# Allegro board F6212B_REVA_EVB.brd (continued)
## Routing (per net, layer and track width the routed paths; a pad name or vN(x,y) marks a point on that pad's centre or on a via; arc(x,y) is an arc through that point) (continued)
VDD: length 39.1
  TOP w0.165: C7.2 v1(43.33,49.58)
  TOP w0.508: C3.2 C4.2 C1.2 35.51,93.58 J16.6
  BOTTOM w0.254: 35.52,92.57 J16.6 ; J16.6 34.5,93.6 ; J16.6 36.55,93.6 ; J16.6 35.52,94.63 ; J16.4 39.09,93.6 ; J16.4 38.06,92.57 ; J16.4 38.06,94.63 ; J16.4 37.04,93.6 ; J29.3 51.69,63.83 ; J29.3 50.66,62.8 ; J29.3 49.63,63.83 ; J29.3 50.66,64.86 ; TP6.1 44.45,52.97 ; TP6.1 45.99,51.44 ; TP6.1 44.45,49.9 ; TP6.1 42.91,51.44 ; 39.58,93.6 J16.2 ; J16.2 41.63,93.6 ; J16.2 40.6,94.63 ; J16.2 40.6,92.57 ; J16.12 28.93,93.6 ; J16.12 27.9,92.57 ; J16.12 27.9,94.63 ; J16.10 30.44,94.63 ; J16.10 30.44,92.57 ; J16.10 31.47,93.6 ; J16.10 29.42,93.6 ; 32.98,92.57 J16.8 ; J16.8 34.01,93.6 ; J16.8 32.98,94.63 ; J16.8 31.96,93.6
  vias: v1(57.63,42.53) v1(57.63,41.5) v1(57.61,40.5) v1(57.89,42.28) v1(57.91,41.25) v1(57.92,40.22) v1(59.93,42.53) v1(60.21,42.27) v1(74.24,54.75) v1(74.26,53.43) v1(74.52,54.5) v1(74.52,53.16) v2(51.48,42.4) v2(51.48,41.4) v2(51.48,40.4) v2(54.48,42.4) v2(54.48,41.4) v2(54.48,40.4)
VDD_CREG: length 56.2
  TOP w0.508: R20.2 53.01,49.96 52.19,50.79 52.19,56.66 TP4.1 53.04,58.94 44.6,67.38 J14.1 ; J14.1 J13.1 J12.1 J11.3 ; J14.1 44.59,77.99 C8.2 42.18,77.98 J15.3 J28.3
VDD_EXT: length 3.4
  TOP w0.254: J29.1 59.03,63.83 TP1.1
VDDB: length 4.6
  TOP w0.508: C21.2 C22.2 C23.2 25.37,93.59 J16.14
  vias: v1(48.08,45.06) v1(48.09,37.52) v1(48.34,45.34) v1(48.37,37.8) v1(48.92,46.08) v1(48.93,36.47) v1(49.2,46.34) v1(49.23,36.77) v1(56.77,46.36) v1(56.77,36.74) v1(57.06,46.06) v1(57.04,36.47) v1(57.63,45.36) v1(57.63,37.8) v1(57.91,45.07) v1(57.9,37.5) v2(50.48,43.4) v2(50.48,39.4) v2(50.98,43.9) v2(50.98,38.9) v2(54.98,43.9) v2(54.98,38.9) v2(55.48,43.4) v2(55.48,39.4)
ADD1: length 46.4
  L2 w0.127: J11.2 55.46,78.68 55.46,77.44 54.27,76.25 50.39,76.25 48.3,74.16 48.3,61.33 53.76,55.87 53.76,46.81 53.87,46.7 53.87,45.87 v1(53.33,45.33)
  BOTTOM w0.165: v2(53.98,42.9) 53.98,44.68 v1(53.33,45.33)
ADD2: length 42.7
  L2 w0.127: J12.2 47.88,75.16 47.88,61.33 53.49,55.71 53.49,46.7 53.62,46.57 53.62,46.15 v1(53.31,45.85)
  BOTTOM w0.165: v1(53.31,45.85) 52.93,45.46 52.93,45.07 53.48,44.51 v2(53.48,42.9)
ADD3: length 41.4
  L2 w0.127: v1(52.21,45.39) 52.9,46.08 52.9,55.44 47.03,61.3 47.03,78.8 J13.2
  BOTTOM w0.165: v1(52.21,45.39) 52.21,44.69 52.98,43.92 v2(52.98,42.9)
ADD4: length 41.5
  L2 w0.127: J14.2 46.6,78.52 46.6,61.28 52.6,55.27 52.6,46.41 v1(52.21,46.01)
  BOTTOM w0.165: v2(52.48,42.9) 52.48,43.96 51.84,44.6 51.84,45.64 v1(52.21,46.01)
ADD5: length 43.2
  L2 w0.127: J15.2 46.16,74.71 46.16,61.28 52.35,55.09 52.35,46.66 51.51,45.82 51.51,45.81 v1(51.47,45.77)
  BOTTOM w0.165: v2(51.98,42.9) 51.98,43.98 51.51,44.45 51.51,45.72 v1(51.47,45.77)
AOUT: length 37.5
  TOP w0.165: R4.2 v1(55.59,71.7)
  L2 w0.254: v3(56.48,41.4) 55.71,41.4 55.23,41.88 55.23,42.95 53.98,44.21 53.98,45.14 54.41,45.57 54.41,46.93 54.25,47.08 54.25,56.46 49.05,61.67 49.05,65.16 v1(55.59,71.7)
CREG: length 4.4
  TOP w0.165: R20.1 52.02,48.22 C9.1 51.87,48.07 51.87,46.18 51.84,46.16 51.84,45.05 U3.A6
CSB: length 46.3
  TOP w0.127: R12.2 R13.2
  TOP w0.165: R30.2 74.43,76.17 73.77,75.51 71.12,75.51 70.03,74.42 70.03,68.89 68.48,67.34 65.53,67.34 53.52,55.32 53.52,55.13 53.48,55.09 53.48,47.79 52.58,46.89 52.58,45 U3.A7
F2232H_CSB: length 3.3
  TOP w0.165: J22.12 72.54,79.55 73.51,78.59 R12.1
F2232H_MODE: length 2.7
  TOP w0.165: R32.1 84.25,78.97 J22.4
F2232H_RESET: length 2.8
  TOP w0.165: R10.1 79.48,78.66 J22.8
F2232H_SCLK: length 3
  TOP w0.165: J22.16 66.6,80.52 65.9,79.82 R14.1
F2232H_SDI: length 4.1
  TOP w0.165: J22.18 64.31,79.91 63.72,79.91 62.4,78.59 R16.1
MODE: length 59.4
  TOP w0.165: R31.2 83.64,77.9 83.64,78.33 82.7,79.27 79.62,79.27 78.89,80 78.89,84.72 78.24,85.37 35.56,85.37 34.11,83.92 R3.1
PPMU_CSB: length 24.1
  TOP w0.165: R30.1 v1(73.34,76.92) ; U4.48 v1(60.15,90.93)
  L2 w0.127: v1(60.15,90.93) 63.96,87.12 68.58,87.12 71.3,84.4 71.3,79.6 73.34,77.56 v1(73.34,76.92)
PPMU_MODE: length 39
  TOP w0.165: R31.1 v1(83.12,77.97) ; U4.57 v1(56.15,95.17)
  L2 w0.127: v1(83.12,77.97) 81.46,79.63 81.46,85.09 77.14,89.41 65.33,89.41 61.7,93.04 58.28,93.04 v1(56.15,95.17)
PPMU_RESET: length 34.4
  TOP w0.165: U4.56 v1(56.95,90.93) ; R33.1 v1(78.32,77.99)
  L2 w0.127: v1(78.32,77.99) 78.92,78.59 78.92,84.68 75.41,88.19 64.95,88.19 60.99,92.15 58.17,92.15 v1(56.95,90.93)
PPMU_SCLK: length 21.7
  TOP w0.165: U4.45 v1(60.95,95.19) ; R28.1 v1(64.77,78.08)
  BOTTOM w0.165: v1(60.95,95.19) 60.95,79.51 62.38,78.08 v1(64.77,78.08)
PPMU_SDI: length 19.9
  TOP w0.165: U4.53 v1(57.75,95.17) ; R27.1 v1(60.46,78.13)
  BOTTOM w0.165: v1(60.46,78.13) 58.9,79.69 58.9,94.02 v1(57.75,95.17)
PPMU_SDO: length 24.6
  TOP w0.165: R29.1 v1(68.87,78.03) ; U4.60 v1(55.35,90.93)
  L2 w0.127: v1(55.35,90.93) 60.03,86.26 67.21,86.26 68.87,84.59 v1(68.87,78.03)
RESET: length 69
  TOP w0.165: v1(79.5,76.78) 79.41,76.87 R33.2 ; R10.2 80.64,77.38 R11.2
  L2 w0.127: v1(53.24,46.36) 53.24,55.56 47.45,61.35 v1(47.45,75.64)
  BOTTOM w0.165: v1(53.24,46.36) 53.24,46.34 52.57,45.68 52.57,44.81 v2(52.98,44.4) ; v1(47.45,75.64) 59.33,75.64 61.11,77.42 78.87,77.42 v1(79.5,76.78)
RF1: length 47.6
  L2 w0.203: v3(50.48,44.9) 50.48,47.9 arc(49.5,52.87) 46.69,57.07 arc(35.35,64.65) 21.97,67.31 v4(14.96,67.31)
RF2: length 47.6
  L2 w0.203: v4(3.51,50.04) 26.75,50.04 arc(30.27,49.34) 33.25,47.35 arc(37.06,44.8) 41.56,43.9 v3(49.48,43.9)
RF3: length 47.6
  L2 w0.203: v4(3.51,32.77) 26.75,32.77 arc(30.27,33.47) 33.25,35.46 arc(37.06,38.01) 41.56,38.9 v3(49.48,38.9)
RF4: length 47.6
  L2 w0.203: v3(50.48,37.9) 50.48,34.9 arc(49.5,29.94) 46.69,25.73 arc(35.35,18.15) 21.97,15.49 v4(14.96,15.49)
RF5: length 47.6
  L2 w0.203: v4(91.01,15.49) 84,15.49 arc(70.62,18.15) 59.28,25.73 arc(56.47,29.94) 55.48,34.9 v3(55.48,37.9)
RF6: length 47.6
  L2 w0.203: v4(102.46,32.77) 79.22,32.77 arc(75.7,33.47) 72.72,35.46 arc(68.91,38.01) 64.41,38.9 v3(56.48,38.9)
RF7: length 47.6
  L2 w0.203: v3(56.48,43.9) 64.41,43.9 arc(68.91,44.8) 72.72,47.35 arc(75.7,49.34) 79.22,50.04 v4(102.46,50.04)
RF8: length 47.6
  L2 w0.203: v4(91.01,67.31) 84,67.31 arc(70.62,64.65) 59.28,57.07 arc(56.47,52.87) 55.48,47.9 v3(55.48,44.9)
RFC1: length 37.5
  L2 w0.203: v4(42.82,3.51) 42.82,8.71 arc(43.4,11.62) 45.05,14.09 49.56,18.6 arc(51.35,21.28) 51.98,24.45 v3(51.98,37.9)
RFC2: length 37.5
  L2 w0.203: v4(63.14,3.51) 63.14,8.71 arc(62.57,11.62) 60.92,14.09 56.41,18.6 arc(54.61,21.28) 53.98,24.45 v3(53.98,37.9)
SCLK: length 46.4
  TOP w0.127: R28.2 R14.2
  TOP w0.165: R14.2 R15.2 ; v1(70.39,74.1) 70.39,68.67 68.61,66.88 65.68,66.88 53.77,54.97 53.77,47.57 52.88,46.68 52.88,45.01 U3.A8 ; v1(65.86,76.84) R28.2
  BOTTOM w0.165: v1(70.39,74.1) 70.39,75.53 69.09,76.84 v1(65.86,76.84)
SDI: length 50.7
  TOP w0.165: U3.A10 54.23,45.15 54.23,46.86 54.43,47.07 54.43,54.46 66.01,66.04 68.91,66.04 71.15,68.28 v1(71.15,72.77) ; R17.2 62.64,77.5 R16.2 61.57,77.44 v1(61.57,76.84)
  BOTTOM w0.165: v1(71.15,72.77) 70.64,72.77 69.88,73.53 69.88,75.31 68.73,76.45 65.46,76.45 65.07,76.84 v1(61.57,76.84)
SDO: length 41.8
  TOP w0.165: U3.A9 53.8,45.21 53.8,47.02 54.13,47.35 54.13,54.74 65.84,66.45 68.71,66.45 70.76,68.5 v1(70.76,74.41) ; R29.2 v1(69.96,76.9)
  BOTTOM w0.165: v1(69.96,76.9) 70.76,76.1 v1(70.76,74.41)
TRIG: length 62.4
  TOP w0.165: J30.1 29.69,80.72 35.52,86.54 79.37,86.54 81.42,84.49 81.42,81.78 J22.6
N411943: length 2.6
  TOP w0.165: R2.1 R1.1 U3.H1
N412142: length 13.5
  TOP w0.165: TP3.1 34.96,42.44 R2.2
N417748: length 52.6
  TOP w0.165: R3.2 34.12,80.52 J28.2
  L2 w0.127: v1(51.47,46.38) 51.47,46.39 52.07,46.99 52.07,48.68 51.59,49.16 51.59,49.5 52.01,49.92 52.01,54.99 45.75,61.25 45.75,70.79 J28.2
  BOTTOM w0.165: v1(51.47,46.38) 51.08,45.99 51.08,44.35 51.36,44.07 51.36,43.19 50.95,42.79 50.95,39.89 51.31,39.54 52.63,39.54 52.98,39.89 v2(52.98,39.9)
N421198: length 3.1
  TOP w0.165: R25.2 53.92,70.69 R4.1 53.92,73.7 J26.1
N421279: length 2.1
  TOP w0.165: R5.2 51.42,71.69 J26.2
N422340: length 3.6
  TOP w0.165: R6.2 55.49,68.11 R7.1 55.45,69.14 C13.2 53.98,69.16 U2.4
N422374: length 10.5
  TOP w0.165: U2.1 52,66.19 52.4,65.79 55.19,65.79 R6.1 56.21,66.08 57.34,67.21 57.34,68.39 C13.1 R9.2
N464793: length 7.9
  TOP w0.165: C10.2 51.22,69.23 ; 51.22,69.23 51.98,69.23 U2.5 ; 51.22,69.23 51.17,69.18 51.17,65.86 J29.2
N485360: length 3
  TOP w0.165: J22.14 R18.1 R19.2
N575389: length 1.4
  TOP w0.127: C20.1 61.21,42.41 R26.2
N719451: length 1
  TOP w0.165: R15.1 C15.2
N722947: length 1.1
  TOP w0.165: R19.1 72.17,77.55 C17.2
N724495: length 1.3
  TOP w0.127: R13.1 C14.2
N739084: length 1.3
  TOP w0.165: R11.1 C12.2
N4197900: length 4.1
  TOP w0.165: R25.1 52.81,68.49 53.9,67.4 U2.3
N4219901: length 8.8
  TOP w0.165: J21.1 65.33,72.07 58.71,72.07 57.66,71.02 R9.1

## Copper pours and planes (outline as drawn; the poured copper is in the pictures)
GND on TOP (solid shape): outline of 205 points within 0,43.69 7.47,56.39
GND on TOP (solid shape): outline of 205 points within 98.5,26.42 105.97,39.12
GND on TOP (solid shape): outline of 207 points within 0,26.42 7.47,39.12
GND on TOP (solid shape): outline of 207 points within 98.5,43.69 105.97,56.39
GND on TOP (solid shape): outline of 211 points within 87.05,60.96 94.51,73.66
GND on TOP (solid shape): outline of 220 points within 11.46,60.96 18.92,73.66
GND on TOP (solid shape): outline of 220 points within 11.46,9.14 18.92,21.84
GND on TOP (solid shape): outline of 220 points within 36.47,0 49.17,7.47
GND on TOP (solid shape): outline of 220 points within 56.79,0 69.49,7.47
GND on TOP (solid shape): outline of 220 points within 87.05,9.14 94.51,21.84
GND on TOP: 11.46,25.41 0,25.41 0,26.78 7.19,26.78 7.18,38.75 0,38.75 0,44.07 7.15,44.07 7.15,55.99 0,55.99 0,57.39 11.46,57.39 11.46,61.14 18.57,61.14 18.55,73.48 11.46,73.48 11.46,100.44 94.51,100.44 94.51,73.29 87.3,73.29 87.29,61.33 94.51,61.31 94.51,57.39 105.97,57.39 105.97,56.02 98.87,56.02 98.84,44.04 105.97,44.04 105.97,38.73 98.75,38.75 98.79,26.81 105.97,26.81 105.95,25.41 94.51,25.41 94.51,21.46 87.35,21.46 87.35,9.54 94.48,9.54 94.51,0 69.13,0 69.13,7.18 57.2,7.17 57.21,0 48.81,0 48.8,7.13 36.84,7.12 36.84,0 11.46,0 11.46,9.56 18.54,9.56 18.54,21.44 11.46,21.44
GND on BOTTOM, L3: 11.46,25.41 0,25.41 0,57.39 11.46,57.39 11.46,100.44 94.51,100.44 94.51,57.39 105.97,57.39 105.97,25.41 94.51,25.41 94.51,0 11.46,0
GND on L2: 7.47,56.39 0,56.39 0,43.69 7.47,43.69 7.47,49.71 3.76,49.71 3.09,50.04 3.76,50.37 7.47,50.37
GND on L2: 56.79,7.47 56.79,0 69.49,0 69.49,7.47 63.47,7.47 63.47,3.76 63.14,3.09 62.81,3.76 62.81,7.47
GND on L2: 98.49,26.42 105.96,26.42 105.96,39.12 98.49,39.12 98.49,33.1 102.19,33.1 102.86,32.77 102.19,32.44 98.49,32.44
GND on L2: 18.92,73.66 11.46,73.66 11.46,60.96 18.92,60.96 18.92,66.98 15.22,66.98 14.55,67.31 15.22,67.64 18.92,67.64
GND on L2: 98.5,43.69 105.96,43.69 105.96,56.39 98.5,56.39 98.5,50.37 102.2,50.37 102.87,50.04 102.2,49.71 98.5,49.71
GND on L2: 7.47,39.12 0,39.12 0,26.42 7.47,26.42 7.47,32.44 3.76,32.44 3.09,32.77 3.76,33.1 7.47,33.1
GND on L2: 11.46,25.41 0,25.41 0,26.78 7.19,26.78 7.18,38.75 0,38.75 0,44.07 7.15,44.07 7.15,55.99 0,55.99 0,57.39 11.46,57.39 11.46,61.33 18.47,61.33 18.45,73.27 11.46,73.27 11.46,100.44 94.51,100.44 94.51,73.29 87.3,73.29 87.29,61.33 94.51,61.31 94.51,57.39 105.97,57.39 105.97,56.02 98.82,56.02 98.79,44.04 105.97,44.04 105.97,38.73 98.75,38.75 98.79,26.81 105.97,26.81 105.95,25.41 94.51,25.41 94.51,21.46 87.35,21.46 87.35,9.54 94.48,9.54 94.51,0 69.13,0 69.13,7.18 57.2,7.17 57.21,0 48.81,0 48.8,7.13 36.84,7.12 36.84,0 11.46,0 11.46,9.56 18.59,9.56 18.59,21.44 11.46,21.44 ; 10 cut-outs
GND on L2: 87.05,60.96 94.51,60.96 94.51,73.66 87.05,73.66 87.05,67.64 90.75,67.64 91.42,67.31 90.75,66.98 87.05,66.98
GND on L2: 18.92,21.84 11.45,21.84 11.45,9.14 18.92,9.14 18.92,15.16 15.22,15.16 14.55,15.49 15.22,15.82 18.92,15.82
GND on L2: 36.47,7.47 36.47,0 49.17,0 49.17,7.47 43.15,7.47 43.15,3.76 42.82,3.09 42.49,3.76 42.49,7.47
GND on L2: 87.05,9.14 94.51,9.14 94.51,21.84 87.05,21.84 87.05,15.82 90.75,15.82 91.42,15.49 90.75,15.16 87.05,15.16
VDD on BOTTOM: 26.95,94.87 42.32,94.87 42.32,91.52 33.5,82.7 33.5,71.27 39.52,65.25 70.74,65.25 74.83,61.16 74.83,43.76 71.12,40.06 53.26,40.06 53.14,40.18 52.84,40.18 52.72,40.06 51.31,40.06 51.16,40.21 51.16,42.37 51.38,42.6 54.28,42.6 54.43,42.75 56.24,42.75 57.63,44.15 59.28,44.15 59.28,50.67 48.16,50.67 47.55,50.68 43.7,46.86 38.13,46.86 26.95,58.04
VDDB on BOTTOM: 20.02,94.77 26.57,94.77 26.57,89.7 26.21,89.23 26.21,57.63 37.62,46.23 43.97,46.23 47.8,50.06 58.6,50.06 58.6,44.65 57.43,44.65 55.8,43.03 55.24,43.03 53.82,44.47 53.82,46.66 50.93,46.66 50.93,44.81 51.31,44.38 51.31,43.49 50.72,42.9 50.72,39.8 51.33,39.19 54.58,39.19 55.19,39.8 55.78,39.8 56.16,39.42 58.42,39.42 58.42,34.06 57.66,33.3 34.9,33.3 20.02,48.18
(no net) on TOP: 102.75,50.34 105.08,50.34 105.97,50.54 105.97,56.39 98.5,56.39 98.5,43.69 105.97,43.69 105.97,49.54 105.08,49.73 102.75,49.73 102.66,49.67 102.56,49.63 102.45,49.62 102.35,49.63 102.25,49.68 102.16,49.74 102.1,49.83 102.06,49.93 102.04,50.04 102.06,50.15 102.1,50.25 102.16,50.33 102.25,50.4 102.35,50.44 102.45,50.46 102.56,50.45 102.66,50.41
(no net) on TOP: 14.67,15.19 12.34,15.19 11.46,15 11.46,9.14 18.92,9.14 18.92,21.84 11.46,21.84 11.46,15.99 12.34,15.8 14.67,15.8 14.76,15.86 14.86,15.9 14.97,15.91 15.08,15.9 15.18,15.85 15.26,15.79 15.33,15.7 15.37,15.6 15.38,15.49 15.37,15.39 15.33,15.29 15.26,15.2 15.18,15.13 15.08,15.09 14.97,15.07 14.86,15.09 14.76,15.13
(no net) on TOP: 3.22,49.73 0.89,49.73 0,49.54 0,43.69 7.47,43.69 7.47,56.39 0,56.39 0,50.54 0.89,50.34 3.22,50.34 3.31,50.41 3.41,50.45 3.51,50.46 3.62,50.44 3.72,50.4 3.81,50.33 3.87,50.25 3.91,50.15 3.93,50.04 3.91,49.93 3.87,49.83 3.81,49.74 3.72,49.68 3.62,49.63 3.51,49.62 3.41,49.63 3.31,49.67
(no net) on TOP: 102.75,33.07 105.08,33.07 105.97,33.26 105.97,39.12 98.5,39.12 98.5,26.42 105.97,26.42 105.97,32.27 105.08,32.46 102.75,32.46 102.66,32.4 102.56,32.36 102.45,32.35 102.35,32.36 102.25,32.41 102.16,32.47 102.1,32.56 102.06,32.66 102.04,32.77 102.06,32.87 102.1,32.97 102.16,33.06 102.25,33.13 102.35,33.17 102.45,33.19 102.56,33.17 102.66,33.13
(no net) on TOP: 91.3,15.8 93.62,15.8 94.51,15.99 94.51,21.84 87.05,21.84 87.05,9.14 94.51,9.14 94.51,15 93.62,15.19 91.3,15.19 91.21,15.13 91.11,15.09 91,15.07 90.89,15.09 90.79,15.13 90.71,15.2 90.64,15.29 90.6,15.39 90.59,15.49 90.6,15.6 90.64,15.7 90.71,15.79 90.79,15.85 90.89,15.9 91,15.91 91.11,15.9 91.21,15.86
(no net) on TOP: 43.13,3.22 43.13,0.89 43.32,0 49.17,0 49.17,7.47 36.47,7.47 36.47,0 42.33,0 42.52,0.89 42.52,3.22 42.46,3.31 42.42,3.41 42.41,3.51 42.42,3.62 42.46,3.72 42.53,3.81 42.62,3.87 42.72,3.91 42.82,3.93 42.93,3.91 43.03,3.87 43.12,3.81 43.18,3.72 43.23,3.62 43.24,3.51 43.23,3.41 43.19,3.31
(no net) on TOP: 63.45,3.22 63.45,0.89 63.64,0 69.49,0 69.49,7.47 56.79,7.47 56.79,0 62.65,0 62.84,0.89 62.84,3.22 62.78,3.31 62.74,3.41 62.73,3.51 62.74,3.62 62.78,3.72 62.85,3.81 62.94,3.87 63.04,3.91 63.14,3.93 63.25,3.91 63.35,3.87 63.44,3.81 63.5,3.72 63.55,3.62 63.56,3.51 63.55,3.41 63.51,3.31
(no net) on TOP: 14.67,67.01 12.34,67.01 11.46,66.81 11.46,60.96 18.92,60.96 18.92,73.66 11.46,73.66 11.46,67.81 12.34,67.61 14.67,67.61 14.76,67.68 14.86,67.72 14.97,67.73 15.08,67.71 15.18,67.67 15.26,67.6 15.33,67.52 15.37,67.42 15.38,67.31 15.37,67.2 15.33,67.1 15.26,67.02 15.18,66.95 15.08,66.91 14.97,66.89 14.86,66.9 14.76,66.94
(no net) on TOP: 91.29,67.61 93.62,67.61 94.51,67.81 94.51,73.66 87.05,73.66 87.05,60.96 94.51,60.96 94.51,66.81 93.62,67.01 91.29,67.01 91.21,66.94 91.11,66.9 91,66.89 90.89,66.91 90.79,66.95 90.71,67.02 90.64,67.1 90.6,67.2 90.59,67.31 90.6,67.42 90.64,67.52 90.71,67.6 90.79,67.67 90.89,67.71 91,67.73 91.11,67.72 91.21,67.68
(no net) on TOP: 3.22,32.46 0.89,32.46 0,32.27 0,26.42 7.47,26.42 7.47,39.12 0,39.12 0,33.26 0.89,33.07 3.22,33.07 3.31,33.13 3.41,33.17 3.51,33.19 3.62,33.17 3.72,33.13 3.81,33.06 3.87,32.97 3.91,32.87 3.93,32.77 3.91,32.66 3.87,32.56 3.81,32.47 3.72,32.41 3.62,32.36 3.51,32.35 3.41,32.36 3.31,32.4

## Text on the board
Ref Des/Silkscreen Bottom: GND | SDI | SCLK | SDO | CSB | RESET | TRIG | MODE
Ref Des/Silkscreen Top: MODE | ADD5 | ADD4 | ADD3 | ADD2 | ADD1 | GND | PPMU_SDO | PPMU_MODE | PPMU_RESET | PPMU_SDI | PPMU_CSB | PPMU_SCLK | TRIG | REXT | VDD_CREG | VDDB | VDD | AOUT | VDD_EXT | HWE-F62XXB165-A | 02/20 | RF1 | RF2 | RF3 | RF4 | RFC1 | RFC2 | RF5 | RF6 | RF7 | RF8
XSECTION_CHART: STACKUP TABLE | Unit = Mils | # | 1 | 2 | 3 | 4 | NAME | TOP | L2 | L3 | BOTTOM | TYPE | SURFACE | PLANE | DIELECTRIC | CONDUCTOR | MATERIAL | AIR | 0.5_COPPER | MEGTRON6_10_GHZ | 1OZ_COPPER | TOTAL THICKNESS | THICKNESS | 0 | 0.7 | 9 | 1.4 | 10 | 41 | 64.2
User.9: FIGURE | FINISHED_SIZE | 5.11 | 6.0 | DRILL CHART: TOP to L2 | ALL UNITS ARE IN MILS | TOLERANCE_DRILL | +2.36/-2.36 | +3.0/-3.0 | PLATED | QTY | 11 | 10
User.10: FIGURE | FINISHED_SIZE | 5.11 | 6.0 | DRILL CHART: TOP to L3 | ALL UNITS ARE IN MILS | TOLERANCE_DRILL | +2.36/-2.36 | +3.0/-3.0 | PLATED | QTY | 214 | 3546
User.11: FIGURE | FINISHED_SIZE | 5.11 | 6.0 | 24.8 | 40.16 | 45.0 | 65.0 | 75.2 | 129.92 | 57.09 | 80.0 | DRILL CHART: TOP to BOTTOM | ALL UNITS ARE IN MILS | TOLERANCE_DRILL | +2.36/-2.36 | +3.0/-3.0 | +2.99/-2.99 | +2.0/-2.0 | PLATED | NON-PLATED | QTY | 21 | 1868 | 2 | 66 | 8 | 4 | 20
User.12: 14. FILL DRILL FIGURE "6P" WITH SOLDERMASK, THESE ARE 1:3 VIA'S THAT ARE 6 MILS. | 11. GROUND SHAPES EXTENDED TO BOARD EDGE ARE INTENTIONAL. | 12. RoHS COMPLAINT. | 13. FILL 5.11 MIL AND 6 MIL HOLES WITH NON-CONDUCTIVE MATERIAL AND CU PLATE. FLAT PADS WITH NO DIMPLES | NOTES: UNLESS OTHERWISE SPECIFIED: | 10. SERIALIZE BOARDS AS FOLLOWS: "S/N YYYYMM##" YEAR, MONTH-NUMBER. | REQUIRED. OUTGASSING NOT PERMITTED. | THICKNESS 120-240 MICRO-INCHES. GOLD THICKNESS 3-6 MICRO-INCHES. | 4. SURFACE FINISH: ELECTROLESS NICKEL/IMMERSION GOLD PER IPC-4552. NICKEL | CLASS H AND ARTWORK SUPPLIED. ENSURE SOLDERMASK DOES NOT ENCROACH ON SMD LANDS. | COLOR GREEN. | 9. SOLDERABILITY: SOLDERABLITITY TO BE CONFIRMED PER LOT IAW IPC-650. | 6. SILKSCREEN:APPLY NON-CONDUCTIVE/NON-NUTRIENT EPOXY INK PER ARTWORK | SUPPLIED. ENSURE NO LEGEND IS APPLIED OVER SOLDERABLE SURFACES. MARK LOGO | - THE PURCHASE ORDER | - THIS DRAWING | - IPC-6012 SERIES, CURRENT REVISION, CLASS 2. | - IPC-A-600 CURRENT REVISION, CLASS 2. | SHOWN IN CHART REQUIRE 0.001" MINIMUM BARREL PLATING THICHNESS. NOTE | 5. SOLDERMASK: LPI SOLDERMASK SMOBC BOTH SIDES PER IPC-SM-840 CURRENT REVISION. | CU AS NEEDED PER PROCESS AND/OR BOW/TWIST REQUIREMENTS. | IPC-D-356 FORMAT. FINAL PRODUCT TO BE TESTED TRACEABLE TO SAME. | UL RATING AND DATE CODE ON SECONDARY SIDE. | - IPC-7721 CURRENT REVISION, CLASS 2. | 7. ARTWORK: BOARD IS DESIGNED TO NOMINAL 5/5 TECNOLOGY. VENDOR MAY ADD OR REMOVE NON-FUCTIONAL | 8. NETLIST TEST: VENDOR TO PROVE TOOLED GERBER FILES AGAINST SUPPLIED NETLIST IN | 1. APPLICABLE SPECIFICATIONS AND ORDER OF PRECEDENCE: | 3. PLATING: ADDITIONAL CU PLATE APPROX. 1OZ./5QFT. PLATED THROUGH HOLES AS | REFERENCE STACKUP AND REQUIREMENTS BELOW. FLAMMABILITY RATING 94VO REQUIRED. | 2. MATERIAL:MEGTRON 6 COPPER THICKNESS, DIELECTRIC ARRANGEMENT AND THICKNESS PER | MANUFACTURING: | CONNECTOR BODY TO BE FLUSH AGAINST BOARD EDGE. NO AIR GAP'S PERMITTED. | 6. WHEN MOUNTING SMA CONNECTORS ENSURE THAT CONNECTOR PIN IS CENTERED AND FLUSH WITH TRACE. | 5. SOLER TYPE: LEAD FREE. | 4. ASSEMBLE AND SOLDER IN ACCORDANCE TO IPC-610 CLASS II (CURRENT REVISION). | SHIPPING OF THIS ASSEMBLY. | TO THIS A CHAMFERED CONRNER OR AN INDENTED OUTLINE WILL ALSO INDICATE PIN ONE OF | 2. THE FOLLOWING ARE FOR REFERENCE ONLY AND MAY NOT APPEAR ON THE PARTS. | A DEVICE OR CONNECTOR. | COMPONETS WILL BE DISIGNATED AS "DNI". | 3. FOR COMPONETS NOT TO BE INSTALLED REFER TO SCHEMATIC AND BILL OF MATERIALS. THESE | PIN  OR CIRCLE WILL INDICATE THE PIN ONE OF A DEVICE OR CONNTECTOR. IN ADDITION | A PLUS SIGN (+) INDICATES THE POSTIVE END OF A POLARIZED CAPACITOR. A SQUARE | ACCORDANCE TO MIL-STD-1686/IPC-610 CLASS II AND III IN HANDLING, STORAGE AND | 1. CAUTION: ELECTRO STATIC DEVICES: THIS ASSEMBLY CONTAINS PARTS SENSITIVE TO | DAMAGE BY ELECTROSTAATIC DISCHARGE (ESD) USE PRECAUTIONARY PROCEDURES IN | ASSEMBLY:
